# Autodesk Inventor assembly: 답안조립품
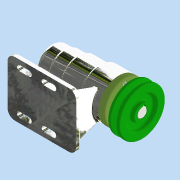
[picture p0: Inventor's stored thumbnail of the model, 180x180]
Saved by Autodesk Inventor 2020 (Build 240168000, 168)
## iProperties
Created: 2021-10
Part Number: 답안조립품
Document SubType Name: Assembly
Designer: user
Author: user
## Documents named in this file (12)
- C:\Users\user\Desktop\711007V1001\답안조립품.iam
- C:\Users\user\Desktop\711007V1001\V벨트풀리.ipt
- C:\Users\user\Desktop\711007V1001\멈춤나사 M3.ipt
- C:\Users\user\Desktop\711007V1001\베어링 6004.ipt
- C:\Users\user\Desktop\711007V1001\베어링 51202.ipt
- C:\Users\user\Desktop\711007V1001\본체.ipt
- C:\Users\user\Desktop\711007V1001\볼트 M4.ipt
- C:\Users\user\Desktop\711007V1001\어댑터슬리브.ipt
- C:\Users\user\Desktop\711007V1001\오일 실 20x35x7.ipt
- C:\Users\user\Desktop\711007V1001\축.ipt
- C:\Users\user\Desktop\711007V1001\커버.ipt
- C:\Users\user\Desktop\711007V1001\키 5x5.ipt
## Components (1 placed, 1 different names)
1. V벨트풀리:1 — 플러쉬:1
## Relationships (1: Flush 1)
- 플러쉬:1 [Flush]: V벨트풀리:1
